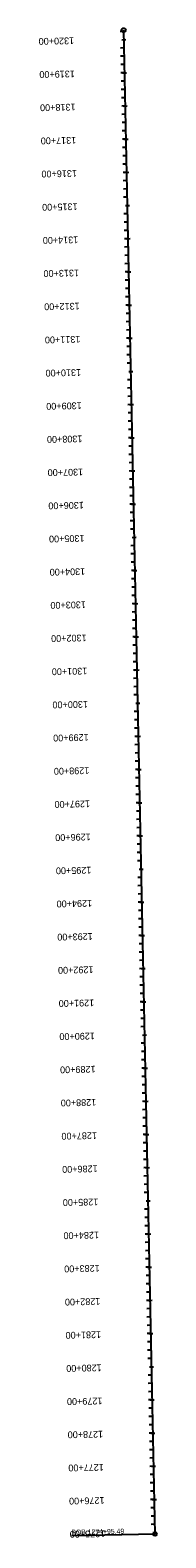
# Model space of a CAD drawing. Extents: x 20505176 to 20507193, y 7960287 to 7982631.
# Drawn here: x 20506359 to 20506715, y 7960287 to 7964831 of the extents above; entities that cross this region are included whole.
import ezdxf

# ---------------------------------------------------------------- set-up
doc = ezdxf.new("R2010")
doc.units = 0
for name, color, linetype in [('Alignment', 7, 'Continuous'), ('Default', 7, 'Continuous'), ('PC_REBAR GL 1', 7, 'Continuous'), ('TextAlignment', 7, 'Continuous'), ('TextAlignmentLrg', 7, 'Continuous'), ('TextAlignmentSml', 7, 'Continuous')]:
    doc.layers.add(name, color=color, linetype=linetype)

msp = doc.modelspace()

# ---------------------------------------------------------------- linework, layer by layer
at = {"layer": 'Alignment'}
msp.add_line((20506708.6, 7960298.4), (20506614.3, 7964830.5), dxfattribs=at)
at = {"layer": 'Default'}
msp.add_line((20506708.6, 7960298.4), (20506614.3, 7964830.5), dxfattribs=at)
at = {"layer": 'PC_REBAR GL 1'}
msp.add_line((20506708.6, 7960298.4), (20506614.3, 7964830.5), dxfattribs=at)
at = {"layer": 'TextAlignment'}
for p in [(20506708.6, 7960298.4), (20506456.7, 7960293.1)]:
    msp.add_line(p, (20506456.7, 7960293.1), dxfattribs=at)
for centre, radius in [((20506614.3, 7964830.5), 6.24), ((20506708.6, 7960298.4), 5.34)]:
    msp.add_circle(centre, radius, dxfattribs=at)
at = {"layer": 'TextAlignmentLrg'}
for p, q in [((20506608.8, 7964801.8), (20506621, 7964802.1)), ((20506617, 7964701.9), (20506606.1, 7964701.7)), ((20506619.1, 7964602), (20506608.2, 7964601.7)), ((20506621.2, 7964502), (20506610.2, 7964501.8)), ((20506623.2, 7964402), (20506612.3, 7964401.8)), ((20506619.2, 7964301.9), (20506631.4, 7964302.2)), ((20506627.4, 7964202.1), (20506616.5, 7964201.8)), ((20506629.5, 7964102.1), (20506618.6, 7964101.8)), ((20506631.6, 7964002.1), (20506620.6, 7964001.9)), ((20506633.6, 7963902.1), (20506622.7, 7963901.9)), ((20506629.6, 7963802), (20506641.8, 7963802.3)), ((20506637.8, 7963702.2), (20506626.9, 7963701.9)), ((20506639.9, 7963602.2), (20506629, 7963602)), ((20506642, 7963502.2), (20506631, 7963502)), ((20506644, 7963402.2), (20506633.1, 7963402)), ((20506640, 7963302.1), (20506652.2, 7963302.4)), ((20506648.2, 7963202.3), (20506637.3, 7963202)), ((20506650.3, 7963102.3), (20506639.4, 7963102.1)), ((20506652.4, 7963002.3), (20506641.4, 7963002.1)), ((20506654.4, 7962902.3), (20506643.5, 7962902.1)), ((20506650.4, 7962802.2), (20506662.6, 7962802.5)), ((20506658.6, 7962702.4), (20506647.7, 7962702.2)), ((20506660.7, 7962602.4), (20506649.8, 7962602.2)), ((20506662.8, 7962502.4), (20506651.8, 7962502.2)), ((20506664.8, 7962402.4), (20506653.9, 7962402.2)), ((20506660.8, 7962302.3), (20506673, 7962302.6)), ((20506669, 7962202.5), (20506658.1, 7962202.3)), ((20506671.1, 7962102.5), (20506660.2, 7962102.3)), ((20506673.2, 7962002.5), (20506662.2, 7962002.3)), ((20506675.2, 7961902.6), (20506664.3, 7961902.3)), ((20506671.2, 7961802.4), (20506683.4, 7961802.7)), ((20506679.4, 7961702.6), (20506668.5, 7961702.4)), ((20506681.5, 7961602.6), (20506670.6, 7961602.4)), ((20506683.6, 7961502.6), (20506672.6, 7961502.4)), ((20506685.6, 7961402.7), (20506674.7, 7961402.4)), ((20506681.6, 7961302.6), (20506693.8, 7961302.8)), ((20506689.8, 7961202.7), (20506678.9, 7961202.5)), ((20506691.9, 7961102.7), (20506681, 7961102.5)), ((20506694, 7961002.7), (20506683, 7961002.5)), ((20506696, 7960902.8), (20506685.1, 7960902.5)), ((20506692, 7960802.7), (20506704.2, 7960802.9)), ((20506700.2, 7960702.8), (20506689.3, 7960702.6)), ((20506702.3, 7960602.8), (20506691.4, 7960602.6)), ((20506704.4, 7960502.9), (20506693.4, 7960502.6)), ((20506706.4, 7960402.9), (20506695.5, 7960402.6)), ((20506702.4, 7960302.8), (20506714.6, 7960303))]:
    msp.add_line(p, q, dxfattribs=at)
at = {"layer": 'TextAlignmentSml'}
for p, q in [((20506614.4, 7964826.9), (20506603.5, 7964826.7)), ((20506615.4, 7964776.9), (20506604.5, 7964776.7)), ((20506608.8, 7964801.8), (20506621, 7964802.1)), ((20506616, 7964751.9), (20506605, 7964751.7)), ((20506616.5, 7964726.9), (20506605.6, 7964726.7)), ((20506617.5, 7964677), (20506606.6, 7964676.7)), ((20506610.9, 7964701.8), (20506623.1, 7964702.1)), ((20506618, 7964652), (20506607.1, 7964651.7)), ((20506618.6, 7964627), (20506607.6, 7964626.7)), ((20506613, 7964601.8), (20506625.2, 7964602.1)), ((20506619.6, 7964577), (20506608.7, 7964576.7)), ((20506620.1, 7964552), (20506609.2, 7964551.8)), ((20506620.6, 7964527), (20506609.7, 7964526.8)), ((20506615, 7964501.9), (20506627.3, 7964502.1)), ((20506621.7, 7964477), (20506610.8, 7964476.8)), ((20506622.2, 7964452), (20506611.3, 7964451.8)), ((20506622.7, 7964427), (20506611.8, 7964426.8)), ((20506617.1, 7964401.9), (20506629.4, 7964402.1)), ((20506623.8, 7964377), (20506612.8, 7964376.8)), ((20506624.3, 7964352), (20506613.4, 7964351.8)), ((20506624.8, 7964327), (20506613.9, 7964326.8)), ((20506625.8, 7964277), (20506614.9, 7964276.8)), ((20506619.2, 7964301.9), (20506631.4, 7964302.2)), ((20506626.4, 7964252), (20506615.4, 7964251.8)), ((20506626.9, 7964227), (20506616, 7964226.8)), ((20506627.9, 7964177.1), (20506617, 7964176.8)), ((20506621.3, 7964201.9), (20506633.5, 7964202.2)), ((20506628.4, 7964152.1), (20506617.5, 7964151.8)), ((20506629, 7964127.1), (20506618, 7964126.8)), ((20506623.4, 7964101.9), (20506635.6, 7964102.2)), ((20506630, 7964077.1), (20506619.1, 7964076.9)), ((20506630.5, 7964052.1), (20506619.6, 7964051.9)), ((20506631, 7964027.1), (20506620.1, 7964026.9)), ((20506625.4, 7964002), (20506637.7, 7964002.2)), ((20506632.1, 7963977.1), (20506621.2, 7963976.9)), ((20506632.6, 7963952.1), (20506621.7, 7963951.9)), ((20506633.1, 7963927.1), (20506622.2, 7963926.9)), ((20506627.5, 7963902), (20506639.8, 7963902.2)), ((20506634.2, 7963877.1), (20506623.2, 7963876.9)), ((20506634.7, 7963852.1), (20506623.8, 7963851.9)), ((20506635.2, 7963827.1), (20506624.3, 7963826.9)), ((20506636.2, 7963777.1), (20506625.3, 7963776.9)), ((20506629.6, 7963802), (20506641.8, 7963802.3)), ((20506636.8, 7963752.2), (20506625.8, 7963751.9)), ((20506637.3, 7963727.2), (20506626.4, 7963726.9)), ((20506638.3, 7963677.2), (20506627.4, 7963676.9)), ((20506631.7, 7963702), (20506643.9, 7963702.3)), ((20506638.8, 7963652.2), (20506627.9, 7963651.9)), ((20506639.4, 7963627.2), (20506628.4, 7963627)), ((20506633.8, 7963602.1), (20506646, 7963602.3)), ((20506640.4, 7963577.2), (20506629.5, 7963577)), ((20506640.9, 7963552.2), (20506630, 7963552)), ((20506641.4, 7963527.2), (20506630.5, 7963527)), ((20506635.8, 7963502.1), (20506648.1, 7963502.3)), ((20506642.5, 7963477.2), (20506631.6, 7963477)), ((20506643, 7963452.2), (20506632.1, 7963452)), ((20506643.5, 7963427.2), (20506632.6, 7963427)), ((20506637.9, 7963402.1), (20506650.2, 7963402.4)), ((20506644.6, 7963377.2), (20506633.6, 7963377)), ((20506645.1, 7963352.2), (20506634.2, 7963352)), ((20506645.6, 7963327.2), (20506634.7, 7963327)), ((20506646.6, 7963277.3), (20506635.7, 7963277)), ((20506640, 7963302.1), (20506652.2, 7963302.4)), ((20506647.2, 7963252.3), (20506636.2, 7963252)), ((20506647.7, 7963227.3), (20506636.8, 7963227)), ((20506648.7, 7963177.3), (20506637.8, 7963177)), ((20506642.1, 7963202.1), (20506654.3, 7963202.4)), ((20506649.2, 7963152.3), (20506638.3, 7963152.1)), ((20506649.8, 7963127.3), (20506638.8, 7963127.1)), ((20506644.2, 7963102.2), (20506656.4, 7963102.4)), ((20506650.8, 7963077.3), (20506639.9, 7963077.1)), ((20506651.3, 7963052.3), (20506640.4, 7963052.1)), ((20506651.8, 7963027.3), (20506640.9, 7963027.1)), ((20506646.2, 7963002.2), (20506658.5, 7963002.4)), ((20506652.9, 7962977.3), (20506642, 7962977.1)), ((20506653.4, 7962952.3), (20506642.5, 7962952.1)), ((20506653.9, 7962927.3), (20506643, 7962927.1)), ((20506648.3, 7962902.2), (20506660.6, 7962902.5)), ((20506655, 7962877.3), (20506644, 7962877.1)), ((20506655.5, 7962852.3), (20506644.6, 7962852.1)), ((20506656, 7962827.4), (20506645.1, 7962827.1)), ((20506657, 7962777.4), (20506646.1, 7962777.1)), ((20506650.4, 7962802.2), (20506662.6, 7962802.5)), ((20506657.6, 7962752.4), (20506646.6, 7962752.1)), ((20506658.1, 7962727.4), (20506647.2, 7962727.1)), ((20506659.1, 7962677.4), (20506648.2, 7962677.2)), ((20506652.5, 7962702.3), (20506664.7, 7962702.5)), ((20506659.6, 7962652.4), (20506648.7, 7962652.2)), ((20506660.2, 7962627.4), (20506649.2, 7962627.2)), ((20506654.6, 7962602.3), (20506666.8, 7962602.5)), ((20506661.2, 7962577.4), (20506650.3, 7962577.2)), ((20506661.7, 7962552.4), (20506650.8, 7962552.2)), ((20506662.2, 7962527.4), (20506651.3, 7962527.2)), ((20506656.6, 7962502.3), (20506668.9, 7962502.5)), ((20506663.3, 7962477.4), (20506652.4, 7962477.2)), ((20506663.8, 7962452.4), (20506652.9, 7962452.2)), ((20506664.3, 7962427.4), (20506653.4, 7962427.2)), ((20506658.7, 7962402.3), (20506671, 7962402.6)), ((20506665.4, 7962377.4), (20506654.4, 7962377.2)), ((20506665.9, 7962352.5), (20506655, 7962352.2)), ((20506666.4, 7962327.5), (20506655.5, 7962327.2)), ((20506667.4, 7962277.5), (20506656.5, 7962277.2)), ((20506660.8, 7962302.3), (20506673, 7962302.6)), ((20506668, 7962252.5), (20506657, 7962252.2)), ((20506668.5, 7962227.5), (20506657.6, 7962227.3)), ((20506669.5, 7962177.5), (20506658.6, 7962177.3)), ((20506662.9, 7962202.4), (20506675.1, 7962202.6)), ((20506670, 7962152.5), (20506659.1, 7962152.3)), ((20506670.6, 7962127.5), (20506659.6, 7962127.3)), ((20506665, 7962102.4), (20506677.2, 7962102.6)), ((20506671.6, 7962077.5), (20506660.7, 7962077.3)), ((20506672.1, 7962052.5), (20506661.2, 7962052.3)), ((20506672.6, 7962027.5), (20506661.7, 7962027.3)), ((20506667, 7962002.4), (20506679.3, 7962002.7)), ((20506673.7, 7961977.5), (20506662.8, 7961977.3)), ((20506674.2, 7961952.5), (20506663.3, 7961952.3)), ((20506674.7, 7961927.5), (20506663.8, 7961927.3)), ((20506669.1, 7961902.4), (20506681.4, 7961902.7)), ((20506675.8, 7961877.6), (20506664.8, 7961877.3)), ((20506676.3, 7961852.6), (20506665.4, 7961852.3)), ((20506676.8, 7961827.6), (20506665.9, 7961827.3)), ((20506677.8, 7961777.6), (20506666.9, 7961777.4)), ((20506671.2, 7961802.4), (20506683.4, 7961802.7)), ((20506678.4, 7961752.6), (20506667.4, 7961752.4)), ((20506678.9, 7961727.6), (20506668, 7961727.4)), ((20506679.9, 7961677.6), (20506669, 7961677.4)), ((20506673.3, 7961702.5), (20506685.5, 7961702.7)), ((20506680.4, 7961652.6), (20506669.5, 7961652.4)), ((20506681, 7961627.6), (20506670, 7961627.4)), ((20506675.4, 7961602.5), (20506687.6, 7961602.7)), ((20506682, 7961577.6), (20506671.1, 7961577.4)), ((20506682.5, 7961552.6), (20506671.6, 7961552.4)), ((20506683, 7961527.6), (20506672.1, 7961527.4)), ((20506677.4, 7961502.5), (20506689.7, 7961502.8)), ((20506684.1, 7961477.6), (20506673.2, 7961477.4)), ((20506684.6, 7961452.6), (20506673.7, 7961452.4)), ((20506685.1, 7961427.7), (20506674.2, 7961427.4)), ((20506679.5, 7961402.5), (20506691.8, 7961402.8)), ((20506686.2, 7961377.7), (20506675.2, 7961377.4)), ((20506686.7, 7961352.7), (20506675.8, 7961352.4)), ((20506687.2, 7961327.7), (20506676.3, 7961327.4)), ((20506688.2, 7961277.7), (20506677.3, 7961277.5)), ((20506681.6, 7961302.6), (20506693.8, 7961302.8)), ((20506688.8, 7961252.7), (20506677.8, 7961252.5)), ((20506689.3, 7961227.7), (20506678.4, 7961227.5)), ((20506690.3, 7961177.7), (20506679.4, 7961177.5)), ((20506683.7, 7961202.6), (20506695.9, 7961202.8)), ((20506690.8, 7961152.7), (20506679.9, 7961152.5)), ((20506691.4, 7961127.7), (20506680.4, 7961127.5)), ((20506685.8, 7961102.6), (20506698, 7961102.9)), ((20506692.4, 7961077.7), (20506681.5, 7961077.5)), ((20506692.9, 7961052.7), (20506682, 7961052.5)), ((20506693.4, 7961027.7), (20506682.5, 7961027.5)), ((20506687.8, 7961002.6), (20506700.1, 7961002.9)), ((20506694.5, 7960977.8), (20506683.6, 7960977.5)), ((20506695, 7960952.8), (20506684.1, 7960952.5)), ((20506695.5, 7960927.8), (20506684.6, 7960927.5)), ((20506689.9, 7960902.6), (20506702.2, 7960902.9)), ((20506696.6, 7960877.8), (20506685.6, 7960877.5)), ((20506697.1, 7960852.8), (20506686.2, 7960852.6)), ((20506697.6, 7960827.8), (20506686.7, 7960827.6)), ((20506698.6, 7960777.8), (20506687.7, 7960777.6)), ((20506692, 7960802.7), (20506704.2, 7960802.9)), ((20506699.2, 7960752.8), (20506688.2, 7960752.6)), ((20506699.7, 7960727.8), (20506688.8, 7960727.6)), ((20506700.7, 7960677.8), (20506689.8, 7960677.6)), ((20506694.1, 7960702.7), (20506706.3, 7960702.9)), ((20506701.2, 7960652.8), (20506690.3, 7960652.6)), ((20506701.8, 7960627.8), (20506690.8, 7960627.6)), ((20506696.2, 7960602.7), (20506708.4, 7960603)), ((20506702.8, 7960577.8), (20506691.9, 7960577.6)), ((20506703.3, 7960552.8), (20506692.4, 7960552.6)), ((20506703.8, 7960527.8), (20506692.9, 7960527.6)), ((20506698.2, 7960502.7), (20506710.5, 7960503)), ((20506704.9, 7960477.9), (20506694, 7960477.6)), ((20506705.4, 7960452.9), (20506694.5, 7960452.6)), ((20506705.9, 7960427.9), (20506695, 7960427.6)), ((20506700.3, 7960402.7), (20506712.6, 7960403)), ((20506707, 7960377.9), (20506696, 7960377.7)), ((20506707.5, 7960352.9), (20506696.6, 7960352.7)), ((20506708, 7960327.9), (20506697.1, 7960327.7)), ((20506702.4, 7960302.8), (20506714.6, 7960303))]:
    msp.add_line(p, q, dxfattribs=at)

# ---------------------------------------------------------------- texts
at = {"layer": 'TextAlignment'}
for s, p in [('POB ', (20506456.6, 7960296.4)), ('1274+95.49', (20506505.9, 7960297.5))]:
    msp.add_text(s, height=15, rotation=1.1918, dxfattribs=at).set_placement(p)
at = {"layer": 'TextAlignmentLrg'}
for s, p in [('1320+00', (20506464.7, 7964809)), ('1315+00', (20506475.1, 7964309.1)), ('1310+00', (20506485.5, 7963809.2)), ('1305+00', (20506495.9, 7963309.3)), ('1300+00', (20506506.3, 7962809.4)), ('1295+00', (20506516.7, 7962309.5)), ('1290+00', (20506527.1, 7961809.7)), ('1285+00', (20506537.5, 7961309.8)), ('1280+00', (20506547.9, 7960809.9)), ('1275+00', (20506558.3, 7960310))]:
    msp.add_text(s, height=20.4, rotation=181.1918, dxfattribs=at).set_placement(p)
at = {"layer": 'TextAlignmentSml'}
for s, p in [('1320+00', (20506464.7, 7964809)), ('1319+00', (20506466.8, 7964709)), ('1318+00', (20506468.9, 7964609)), ('1317+00', (20506471, 7964509.1)), ('1316+00', (20506473.1, 7964409.1)), ('1315+00', (20506475.1, 7964309.1)), ('1314+00', (20506477.2, 7964209.1)), ('1313+00', (20506479.3, 7964109.2)), ('1312+00', (20506481.4, 7964009.2)), ('1311+00', (20506483.5, 7963909.2)), ('1310+00', (20506485.5, 7963809.2)), ('1309+00', (20506487.6, 7963709.2)), ('1308+00', (20506489.7, 7963609.3)), ('1307+00', (20506491.8, 7963509.3)), ('1306+00', (20506493.9, 7963409.3)), ('1305+00', (20506495.9, 7963309.3)), ('1304+00', (20506498, 7963209.3)), ('1303+00', (20506500.1, 7963109.4)), ('1302+00', (20506502.2, 7963009.4)), ('1301+00', (20506504.3, 7962909.4)), ('1300+00', (20506506.3, 7962809.4)), ('1299+00', (20506508.4, 7962709.5)), ('1298+00', (20506510.5, 7962609.5)), ('1297+00', (20506512.6, 7962509.5)), ('1296+00', (20506514.7, 7962409.5)), ('1295+00', (20506516.7, 7962309.5)), ('1294+00', (20506518.8, 7962209.6)), ('1293+00', (20506520.9, 7962109.6)), ('1292+00', (20506523, 7962009.6)), ('1291+00', (20506525.1, 7961909.6)), ('1290+00', (20506527.1, 7961809.7)), ('1289+00', (20506529.2, 7961709.7)), ('1288+00', (20506531.3, 7961609.7)), ('1287+00', (20506533.4, 7961509.7)), ('1286+00', (20506535.5, 7961409.7)), ('1285+00', (20506537.5, 7961309.8)), ('1284+00', (20506539.6, 7961209.8)), ('1283+00', (20506541.7, 7961109.8)), ('1282+00', (20506543.8, 7961009.8)), ('1281+00', (20506545.9, 7960909.8)), ('1280+00', (20506547.9, 7960809.9)), ('1279+00', (20506550, 7960709.9)), ('1278+00', (20506552.1, 7960609.9)), ('1277+00', (20506554.2, 7960509.9)), ('1276+00', (20506556.3, 7960410)), ('1275+00', (20506558.3, 7960310))]:
    msp.add_text(s, height=20.4, rotation=181.1918, dxfattribs=at).set_placement(p)

doc.saveas('drawing.dxf')
